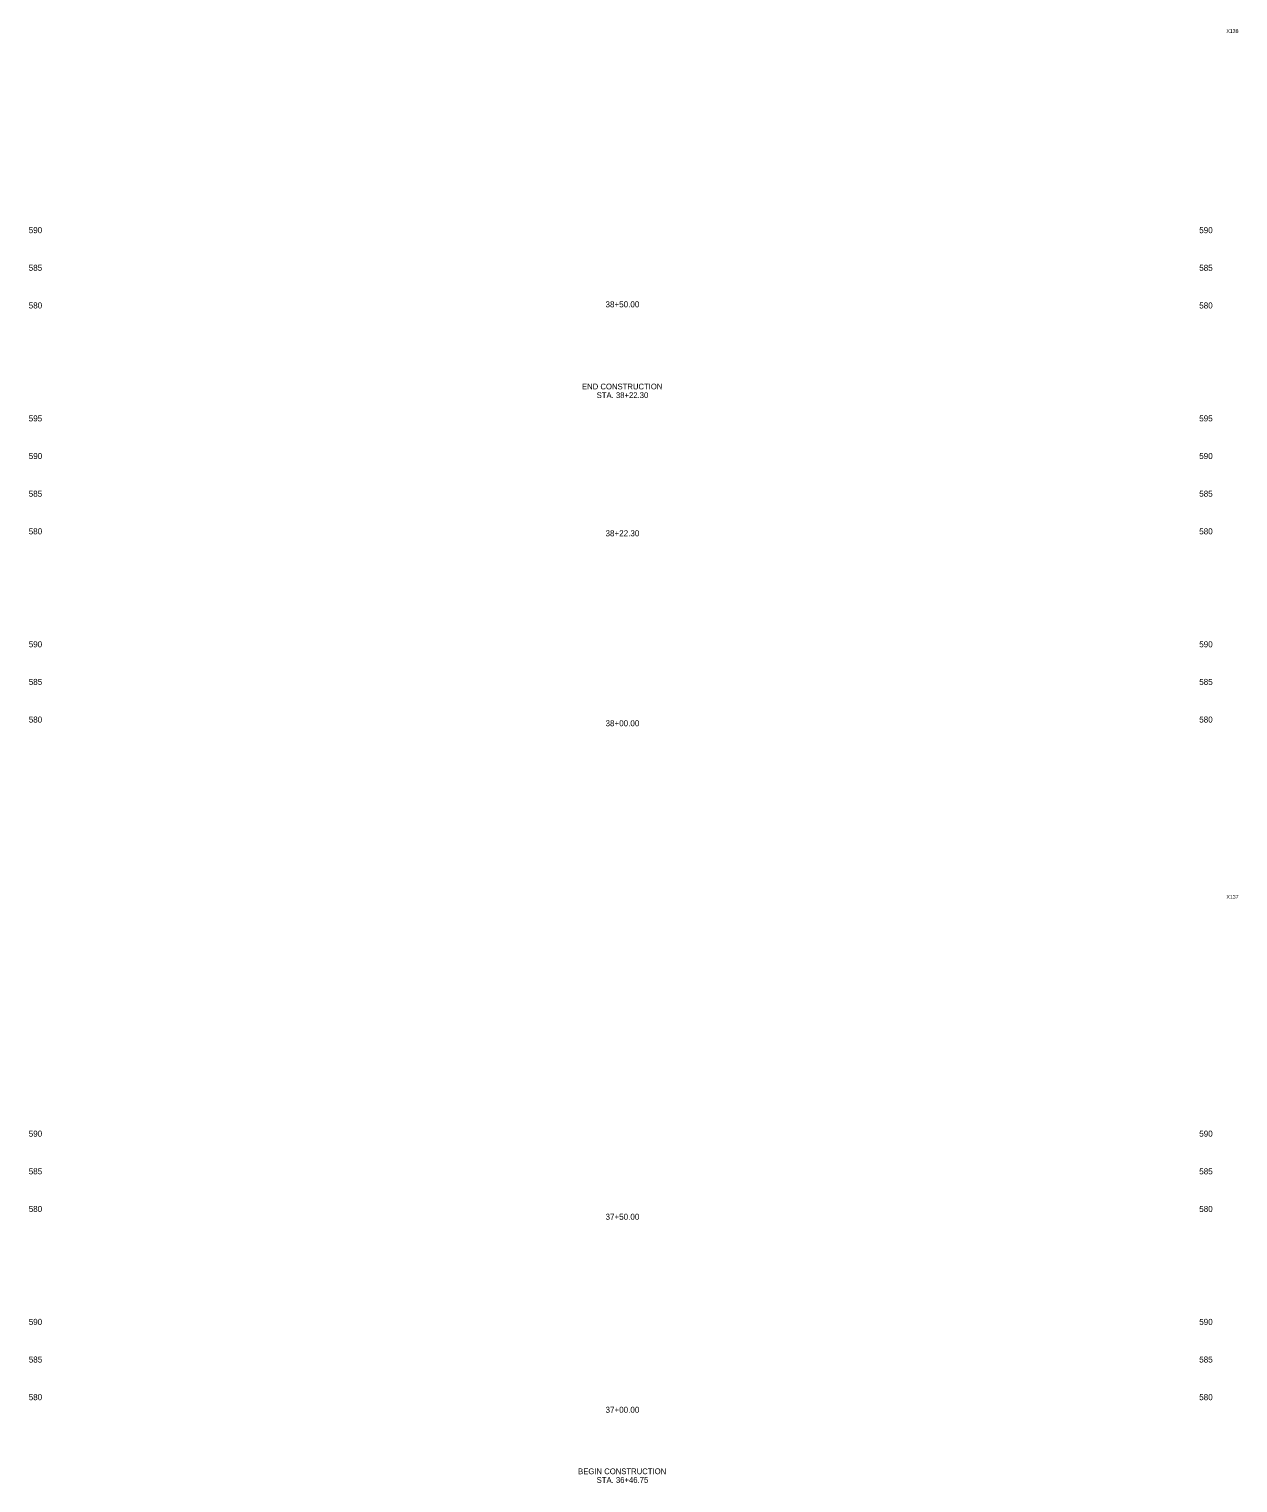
# Model space of a CAD drawing. Extents: x 1002 to 1324, y 1048 to 1434.
import ezdxf

# ---------------------------------------------------------------- set-up
doc = ezdxf.new("R2010")
doc.units = 0
for name, color, linetype in [('RD_GPK_XS_Cell', 7, 'Continuous'), ('RD_XS_Base', 7, 'Continuous'), ('RD_XS_Pave', 7, 'Continuous')]:
    doc.layers.add(name, color=color, linetype=linetype)

msp = doc.modelspace()

# ---------------------------------------------------------------- texts
at = {"layer": 'RD_GPK_XS_Cell'}
for s, p in [('590', (1002.23, 1380)), ('590', (1313.23, 1380)), ('585', (1002.23, 1370)), ('585', (1313.23, 1370)), ('580', (1002.23, 1360)), ('580', (1313.23, 1360)), ('595', (1002.23, 1330)), ('595', (1313.23, 1330)), ('590', (1002.23, 1320)), ('590', (1313.23, 1320)), ('585', (1002.23, 1310)), ('585', (1313.23, 1310)), ('580', (1002.23, 1300)), ('580', (1313.23, 1300)), ('590', (1002.23, 1270)), ('590', (1313.23, 1270)), ('585', (1002.23, 1260)), ('585', (1313.23, 1260)), ('580', (1002.23, 1250)), ('580', (1313.23, 1250)), ('590', (1002.23, 1140)), ('590', (1313.23, 1140)), ('585', (1002.23, 1130)), ('585', (1313.23, 1130)), ('580', (1002.23, 1120)), ('580', (1313.23, 1120)), ('590', (1002.23, 1090)), ('590', (1313.23, 1090)), ('585', (1002.23, 1080)), ('585', (1313.23, 1080)), ('580', (1002.23, 1070)), ('580', (1313.23, 1070))]:
    msp.add_text(s, height=1.6, dxfattribs=at).set_placement(p)
at = {"layer": 'RD_XS_Base'}
for s, height, p in [('X138', 1, (1320.44, 1433.2)), ('END CONSTRUCTION', 1.53, (1149.23, 1338.5)), ('STA. 38+22.30', 1.53, (1153.13, 1336.2)), ('X137', 1, (1320.45, 1203.2)), ('BEGIN CONSTRUCTION', 1.53, (1148.19, 1050.34)), ('STA. 36+46.75', 1.53, (1153.13, 1048.04))]:
    msp.add_text(s, height=height, dxfattribs=at).set_placement(p)
at = {"layer": 'RD_XS_Pave'}
for s, p in [('38+50.00', (1155.48, 1360.3)), ('38+22.30', (1155.48, 1299.48)), ('38+00.00', (1155.48, 1249.02)), ('37+50.00', (1155.48, 1117.92)), ('37+00.00', (1155.48, 1066.65))]:
    msp.add_text(s, height=1.6, dxfattribs=at).set_placement(p)

doc.saveas('drawing.dxf')
